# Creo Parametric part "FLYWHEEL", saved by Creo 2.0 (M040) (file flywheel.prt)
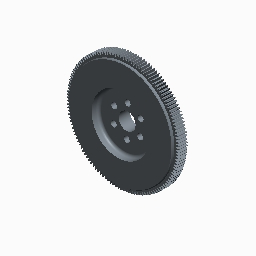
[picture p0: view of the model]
Units: millimeter Kilogram Sec (mmKs); MM, KILOGRAM, SECS

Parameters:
  MATERIAL = "ST37"

Other parameters: D21

Created from: INLBS_PART_SOLID.PRT

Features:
  1. datum plane "SIDE", "RIGHT"
  2. datum plane "DTM1", "TOP"
  3. datum plane "DTM2", "FRONT"
  4. coordinate system "ORIGIN"
  5. datum axis "CRANKSHAFT_CENTER_AXIS"
  6. datum plane "PRESSURE_PLATE_MOUNT"
  7. revolve "Revolve 1", "Section 1"
  8. revolved cut "Revolve 2", "Section 1"
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
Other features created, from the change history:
  group "COPIED_GROUP"
  extrusion "Extrude 1"
  hole "Hole 1"
  pattern "Pattern 1"
  extruded cut "Extrude 2 [1]"
  extruded cut "Extrude 2 [2]"
  extruded cut "Extrude 2 [3]"
  extruded cut "Extrude 2 [4]"
  extruded cut "Extrude 2 [5]"
  extruded cut "Extrude 2 [6]"
  revolved cut "Revolve 3"
  chamfer "Chamfer 1"
  chamfer "Chamfer 2"
  pattern "Pattern 2"
  extruded cut "Extrude 3 [1]"
  extruded cut "Extrude 3 [2]"
  extruded cut "Extrude 3 [3]"
  extruded cut "Extrude 3 [4]"
  extruded cut "Extrude 3 [5]"
  extruded cut "Extrude 3 [6]"
  extruded cut "Extrude 3 [7]"
  extruded cut "Extrude 3 [8]"
  extruded cut "Extrude 3 [9]"
  extruded cut "Extrude 3 [10]"
  extruded cut "Extrude 3 [11]"
  extruded cut "Extrude 3 [12]"
  extruded cut "Extrude 3 [13]"
  extruded cut "Extrude 3 [14]"
  extruded cut "Extrude 3 [15]"
  extruded cut "Extrude 3 [16]"
  extruded cut "Extrude 3 [17]"
  extruded cut "Extrude 3 [18]"
  extruded cut "Extrude 3 [19]"
  extruded cut "Extrude 3 [20]"
  extruded cut "Extrude 3 [21]"
  extruded cut "Extrude 3 [22]"
  extruded cut "Extrude 3 [23]"
  extruded cut "Extrude 3 [24]"
  extruded cut "Extrude 3 [25]"
  extruded cut "Extrude 3 [26]"
  extruded cut "Extrude 3 [27]"
  extruded cut "Extrude 3 [28]"
  extruded cut "Extrude 3 [29]"
  extruded cut "Extrude 3 [30]"
  extruded cut "Extrude 3 [31]"
  extruded cut "Extrude 3 [32]"
  extruded cut "Extrude 3 [33]"
  extruded cut "Extrude 3 [34]"
  extruded cut "Extrude 3 [35]"
  extruded cut "Extrude 3 [36]"
  extruded cut "Extrude 3 [37]"
  extruded cut "Extrude 3 [38]"
  extruded cut "Extrude 3 [39]"
  extruded cut "Extrude 3 [40]"
  extruded cut "Extrude 3 [41]"
  extruded cut "Extrude 3 [42]"
  extruded cut "Extrude 3 [43]"
  extruded cut "Extrude 3 [44]"
  extruded cut "Extrude 3 [45]"
  extruded cut "Extrude 3 [46]"
  extruded cut "Extrude 3 [47]"
  extruded cut "Extrude 3 [48]"
  extruded cut "Extrude 3 [49]"
  extruded cut "Extrude 3 [50]"
  extruded cut "Extrude 3 [51]"
  extruded cut "Extrude 3 [52]"
  extruded cut "Extrude 3 [53]"
  extruded cut "Extrude 3 [54]"
  extruded cut "Extrude 3 [55]"
  extruded cut "Extrude 3 [56]"
  extruded cut "Extrude 3 [57]"
  extruded cut "Extrude 3 [58]"
  extruded cut "Extrude 3 [59]"
  extruded cut "Extrude 3 [60]"
  extruded cut "Extrude 3 [61]"
  extruded cut "Extrude 3 [62]"
  extruded cut "Extrude 3 [63]"
  extruded cut "Extrude 3 [64]"
  extruded cut "Extrude 3 [65]"
  extruded cut "Extrude 3 [66]"
  extruded cut "Extrude 3 [67]"
  extruded cut "Extrude 3 [68]"
  extruded cut "Extrude 3 [69]"
  extruded cut "Extrude 3 [70]"
  extruded cut "Extrude 3 [71]"
  extruded cut "Extrude 3 [72]"
  extruded cut "Extrude 3 [73]"
  extruded cut "Extrude 3 [74]"
  extruded cut "Extrude 3 [75]"
  extruded cut "Extrude 3 [76]"
  extruded cut "Extrude 3 [77]"
  extruded cut "Extrude 3 [78]"
  extruded cut "Extrude 3 [79]"
  extruded cut "Extrude 3 [80]"
  extruded cut "Extrude 3 [81]"
  extruded cut "Extrude 3 [82]"
  extruded cut "Extrude 3 [83]"
  extruded cut "Extrude 3 [84]"
  extruded cut "Extrude 3 [85]"
  extruded cut "Extrude 3 [86]"
  extruded cut "Extrude 3 [87]"
  extruded cut "Extrude 3 [88]"
  extruded cut "Extrude 3 [89]"
  extruded cut "Extrude 3 [90]"
  extruded cut "Extrude 3 [91]"
  extruded cut "Extrude 3 [92]"
  extruded cut "Extrude 3 [93]"
  extruded cut "Extrude 3 [94]"
  extruded cut "Extrude 3 [95]"
  extruded cut "Extrude 3 [96]"
  extruded cut "Extrude 3 [97]"
  extruded cut "Extrude 3 [98]"
  extruded cut "Extrude 3 [99]"
  extruded cut "Extrude 3 [100]"
  extruded cut "Extrude 3 [101]"
  extruded cut "Extrude 3 [102]"
  extruded cut "Extrude 3 [103]"
  extruded cut "Extrude 3 [104]"
  extruded cut "Extrude 3 [105]"
  extruded cut "Extrude 3 [106]"
  extruded cut "Extrude 3 [107]"
  extruded cut "Extrude 3 [108]"
  extruded cut "Extrude 3 [109]"
  extruded cut "Extrude 3 [110]"
  extruded cut "Extrude 3 [111]"
  extruded cut "Extrude 3 [112]"
  extruded cut "Extrude 3 [113]"
  extruded cut "Extrude 3 [114]"
  extruded cut "Extrude 3 [115]"
  extruded cut "Extrude 3 [116]"
  extruded cut "Extrude 3 [117]"
  extruded cut "Extrude 3 [118]"
  extruded cut "Extrude 3 [119]"
  extruded cut "Extrude 3 [120]"
  extruded cut "Extrude 3 [121]"
  extruded cut "Extrude 3 [122]"
  extruded cut "Extrude 3 [123]"
  extruded cut "Extrude 3 [124]"
  extruded cut "Extrude 3 [125]"
  extruded cut "Extrude 3 [126]"
  extruded cut "Extrude 3 [127]"
  extruded cut "Extrude 3 [128]"
  extruded cut "Extrude 3 [129]"
  extruded cut "Extrude 3 [130]"
  extruded cut "Extrude 4"
  round "Round 1"
  round "Round 2"
  round "Round 3"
